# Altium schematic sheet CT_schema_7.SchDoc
size 287 x 160 mm
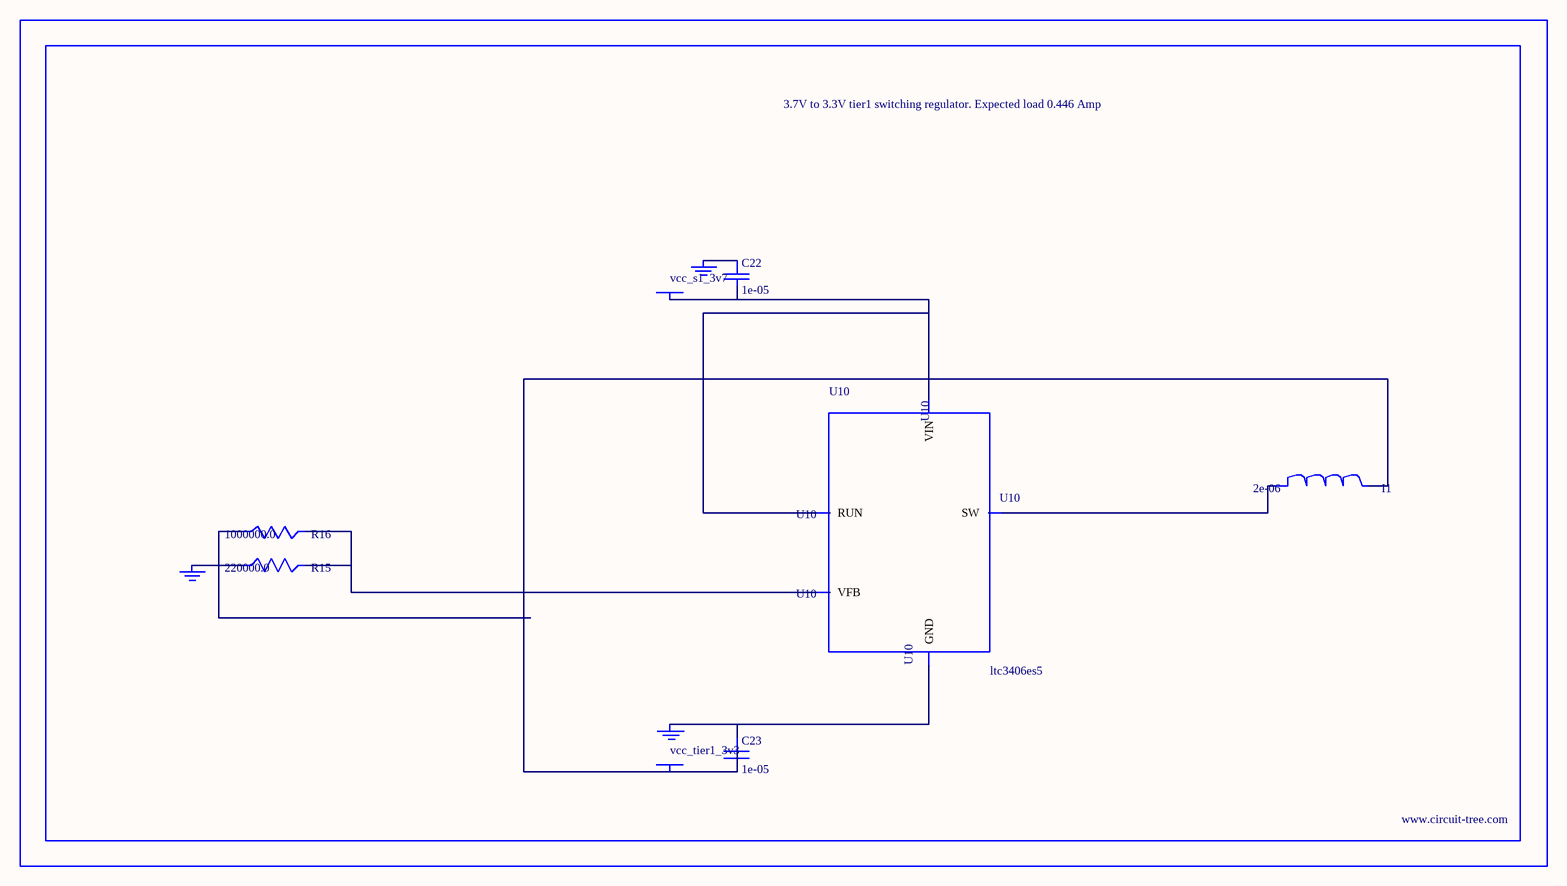
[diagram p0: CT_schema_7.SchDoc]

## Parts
BORDER6  (no value)
C22  1e-05  [C0805]
C23  1e-05  [C0805]
GND_INSTANCE_6_0  (no value)
GND_INSTANCE_6_1  (no value)
GND_INSTANCE_6_2  (no value)
I1  2e-06  [WE-HCI_7030/7040/7050]
POWER_INSTANCE_6_0  vcc_tier1_3v3
POWER_INSTANCE_6_1  vcc_s1_3v7
R15  220000.0  [R0603]
R16  1000000.0  [R0603]
U10  ltc3406es5  [TSOT-23-5]

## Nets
NetC22_1: C22.1 GND_INSTANCE_6_1.0(GND)
NetC22_2: C22.2 POWER_INSTANCE_6_1.0(PWR) U10.1(RUN) U10.4(VIN)
NetC23_1: C23.1 GND_INSTANCE_6_0.0(GND) U10.2(GND)
NetC23_2: C23.2 I1.2 POWER_INSTANCE_6_0.0(PWR) R16.1
NetGND_INSTANCE_6_2_0: GND_INSTANCE_6_2.0(GND) R15.1
NetI1_1: I1.1 U10.3(SW)
NetR15_2: R15.2 R16.2 U10.5(VFB)

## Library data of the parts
BORDER6 = BORDER_PAGE6
C22 C23 = C0805C106K8RACTU
GND_INSTANCE_6_0-GND_INSTANCE_6_2 = GND
I1 = 744314200
POWER_INSTANCE_6_0 POWER_INSTANCE_6_1 = PWR
R15 = RC0603JR-07220KL
R16 = RC0603JR-071ML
